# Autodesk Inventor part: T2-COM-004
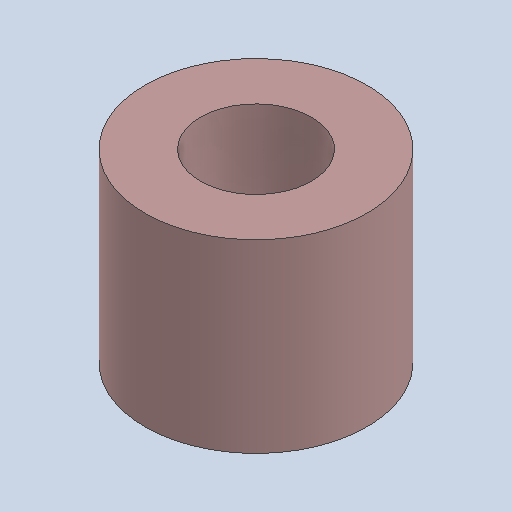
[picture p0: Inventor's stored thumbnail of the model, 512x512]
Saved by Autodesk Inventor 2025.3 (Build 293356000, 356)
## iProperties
Created: 2026-10
Part Number: T2-COM-004
Material: Genérico
Document SubType Name: Modeling
Designer: Luis MuÃ±oz
Density: 1 g/cm^3
Appearance: Valor por defecto
Project: TESIS 2 - Plataforma mecatrÃ³nica preventiva desacoplada
Description: Cojinete liso Ø3 × Ø6 × 5 mm
Author: Luis M
Title: Cojinete liso Ã˜3 Ã— Ã˜6 Ã— 5 mm
Revision Number: 00
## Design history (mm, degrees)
sketch "Boceto1"
  geometry: C1 r 1.5 at (0, 0); C2 r 3 at (0, 0); 1 further point
  constraints: 2 centre point, 2 coincident
  dimensions: "d0" = 3 diameter of C1; "d1" = 6 diameter of C2
extrude "Extrusión1" new body sketch "Boceto1" distance "d2" = 5; taper "d3" = 0 deg
node "Sólido1"
